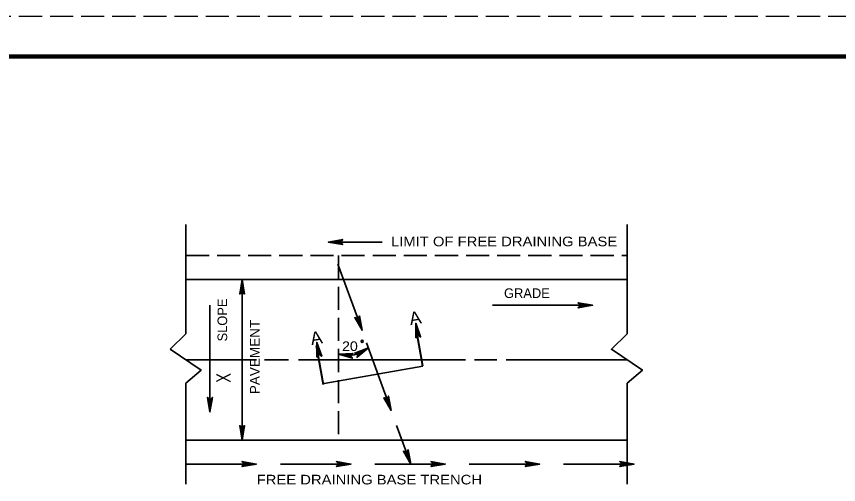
# Model space of a CAD drawing. Extents: x -48732 to -48696.6, y -117659.8 to -117637.8.
# Drawn here: x -48717.26 to -48707.01, y -117643.69 to -117637.85 of the extents above; entities that cross this region are included whole.
import ezdxf

# ---------------------------------------------------------------- set-up
doc = ezdxf.new("R2010")
doc.units = 0
doc.header["$LTSCALE"] = 0.048
doc.linetypes.add('LONG_DASHED', pattern=[7.5, 6, -1.5])
doc.layers.add('1', color=7, linetype='Continuous', lineweight=25)
doc.layers.add('3', color=7, linetype='Continuous', lineweight=35)

msp = doc.modelspace()

# ---------------------------------------------------------------- linework, layer by layer
at = {"layer": '1', "linetype": 'LONG_DASHED'}
msp.add_line((-48696.76492, -117637.84817), (-48731.96492, -117637.84817), dxfattribs=at)
at = {"layer": '1', "lineweight": 158}
msp.add_line((-48696.84825, -117638.34817), (-48729.34825, -117638.34817), dxfattribs=at)
at = {"layer": '1', "lineweight": 40}
for p, q in [((-48712.19542, -117642.21033), (-48712.27867, -117641.73825)), ((-48713.434, -117642.44325), (-48713.51975, -117641.95708))]:
    msp.add_line(p, q, dxfattribs=at)
at = {"layer": '3'}
for p, q in [((-48709.64742, -117640.44458), (-48709.64742, -117641.80458)), ((-48713.37342, -117640.66158), (-48712.70242, -117640.66158)), ((-48713.25242, -117640.93658), (-48712.95242, -117641.76258)), ((-48715.14742, -117641.13058), (-48709.64742, -117641.13058)), ((-48714.44742, -117641.13058), (-48714.44742, -117643.13058)), ((-48714.84742, -117641.44858), (-48714.84742, -117642.77958)), ((-48711.32742, -117641.45058), (-48710.07842, -117641.45058)), ((-48712.89542, -117641.91858), (-48712.58942, -117642.76258)), ((-48715.14742, -117642.13058), (-48714.26842, -117642.13058)), ((-48714.16742, -117642.13058), (-48713.86942, -117642.13058)), ((-48713.74442, -117642.13058), (-48711.66042, -117642.13058)), ((-48711.55042, -117642.13058), (-48711.27142, -117642.13058)), ((-48711.15642, -117642.13058), (-48709.64742, -117642.13058)), ((-48713.42542, -117642.42717), (-48712.19542, -117642.21033)), ((-48715.14742, -117642.42358), (-48715.14742, -117643.68158)), ((-48709.64742, -117642.42358), (-48709.64742, -117643.68158)), ((-48712.52142, -117642.94858), (-48712.34542, -117643.43058)), ((-48715.14742, -117643.13058), (-48709.64742, -117643.13058)), ((-48715.14742, -117643.43058), (-48714.26842, -117643.43058)), ((-48713.97042, -117643.43058), (-48713.09142, -117643.43058)), ((-48713.97042, -117643.43058), (-48713.09142, -117643.43058)), ((-48712.79342, -117643.43058), (-48711.91442, -117643.43058)), ((-48712.79342, -117643.43058), (-48711.91442, -117643.43058)), ((-48711.61642, -117643.43058), (-48710.73742, -117643.43058)), ((-48711.61642, -117643.43058), (-48710.73742, -117643.43058)), ((-48710.43942, -117643.43058), (-48709.56042, -117643.43058)), ((-48710.43942, -117643.43058), (-48709.56042, -117643.43058))]:
    msp.add_line(p, q, dxfattribs=at)
at = {"layer": '3', "linetype": 'LONG_DASHED'}
for p, q in [((-48715.14742, -117640.83058), (-48709.64742, -117640.83058)), ((-48713.24742, -117640.83058), (-48713.24742, -117643.13058))]:
    msp.add_line(p, q, dxfattribs=at)
at = {"layer": '3'}
for points in [[(-48715.14742, -117640.44458), (-48715.14742, -117641.80458), (-48715.34342, -117641.99858)], [(-48713.19342, -117640.63158), (-48713.37342, -117640.66158), (-48713.19342, -117640.69158), (-48713.19842, -117640.68758), (-48713.35542, -117640.66158), (-48713.19742, -117640.63558), (-48713.20242, -117640.63958), (-48713.33642, -117640.66158), (-48713.20242, -117640.68358), (-48713.20742, -117640.68058), (-48713.31842, -117640.66158), (-48713.20742, -117640.64258), (-48713.21142, -117640.64658), (-48713.30042, -117640.66158), (-48713.21142, -117640.67658), (-48713.21642, -117640.67258), (-48713.28242, -117640.66158), (-48713.21642, -117640.65058), (-48713.22042, -117640.65458), (-48713.26342, -117640.66158), (-48713.22042, -117640.66858), (-48713.22542, -117640.66458), (-48713.24542, -117640.66158), (-48713.22542, -117640.65858), (-48713.19342, -117640.63158), (-48713.22942, -117640.66158), (-48713.19342, -117640.69158)], [(-48714.41742, -117641.31058), (-48714.44742, -117641.13058), (-48714.47742, -117641.31058), (-48714.47342, -117641.30558), (-48714.44742, -117641.14858), (-48714.42142, -117641.30658), (-48714.42542, -117641.30158), (-48714.44742, -117641.16758), (-48714.46942, -117641.30158), (-48714.46642, -117641.29658), (-48714.44742, -117641.18558), (-48714.42842, -117641.29658), (-48714.43242, -117641.29258), (-48714.44742, -117641.20358), (-48714.46242, -117641.29258), (-48714.45842, -117641.28758), (-48714.44742, -117641.22158), (-48714.43642, -117641.28758), (-48714.44042, -117641.28358), (-48714.44742, -117641.24058), (-48714.45442, -117641.28358), (-48714.45042, -117641.27858), (-48714.44742, -117641.25858), (-48714.44442, -117641.27858), (-48714.41742, -117641.31058), (-48714.44742, -117641.27458), (-48714.47742, -117641.31058)], [(-48710.25842, -117641.48058), (-48710.07842, -117641.45058), (-48710.25842, -117641.42058), (-48710.25342, -117641.42458), (-48710.09642, -117641.45058), (-48710.25442, -117641.47658), (-48710.24942, -117641.47258), (-48710.11542, -117641.45058), (-48710.24942, -117641.42858), (-48710.24442, -117641.43158), (-48710.13342, -117641.45058), (-48710.24442, -117641.46958), (-48710.24042, -117641.46558), (-48710.15142, -117641.45058), (-48710.24042, -117641.43558), (-48710.23542, -117641.43958), (-48710.16942, -117641.45058), (-48710.23542, -117641.46158), (-48710.23142, -117641.45758), (-48710.18842, -117641.45058), (-48710.23142, -117641.44358), (-48710.22642, -117641.44758), (-48710.20642, -117641.45058), (-48710.22642, -117641.45358), (-48710.25842, -117641.48058), (-48710.22242, -117641.45058), (-48710.25842, -117641.42058)], [(-48713.04242, -117641.60358), (-48712.95242, -117641.76258), (-48712.98542, -117641.58358), (-48712.98742, -117641.58858), (-48712.95842, -117641.74558), (-48713.03742, -117641.60658), (-48713.03242, -117641.60958), (-48712.96442, -117641.72858), (-48712.98942, -117641.59458), (-48712.99142, -117641.59958), (-48712.97142, -117641.71158), (-48713.02642, -117641.61258), (-48713.02142, -117641.61558), (-48712.97742, -117641.69358), (-48712.99342, -117641.60558), (-48712.99542, -117641.61158), (-48712.98342, -117641.67658), (-48713.01642, -117641.61858), (-48713.01142, -117641.62158), (-48712.98942, -117641.65958), (-48712.99742, -117641.61658), (-48712.99942, -117641.62258), (-48712.99642, -117641.64258), (-48713.00642, -117641.62458), (-48713.04242, -117641.60358), (-48713.00142, -117641.62758), (-48712.98542, -117641.58358)], [(-48712.22217, -117641.846), (-48712.283, -117641.67392), (-48712.28133, -117641.85642), (-48712.27825, -117641.85083), (-48712.27992, -117641.69167), (-48712.22683, -117641.84275), (-48712.23167, -117641.8385), (-48712.27658, -117641.71042), (-48712.275, -117641.84617), (-48712.27292, -117641.84075), (-48712.27342, -117641.72808), (-48712.2355, -117641.83408), (-48712.24008, -117641.83083), (-48712.27033, -117641.74583), (-48712.26967, -117641.83608), (-48712.26658, -117641.8305), (-48712.26717, -117641.76358), (-48712.24492, -117641.82667), (-48712.24958, -117641.82342), (-48712.26392, -117641.78225), (-48712.26333, -117641.82583), (-48712.26025, -117641.82025), (-48712.26075, -117641.8), (-48712.25433, -117641.81917), (-48712.22217, -117641.846), (-48712.258, -117641.81575), (-48712.28133, -117641.85642)], [(-48709.64742, -117641.80458), (-48709.84342, -117641.99858), (-48709.45742, -117642.25958), (-48709.64642, -117642.42358)], [(-48713.45492, -117642.08625), (-48713.51575, -117641.91417), (-48713.51408, -117642.09667), (-48713.511, -117642.09108), (-48713.51267, -117641.93192), (-48713.45958, -117642.083), (-48713.46442, -117642.07875), (-48713.50933, -117641.95067), (-48713.50775, -117642.08642), (-48713.50567, -117642.081), (-48713.50617, -117641.96833), (-48713.46825, -117642.07433), (-48713.47283, -117642.07108), (-48713.50308, -117641.98608), (-48713.50242, -117642.07633), (-48713.49933, -117642.07075), (-48713.49992, -117642.00383), (-48713.47767, -117642.06692), (-48713.48233, -117642.06367), (-48713.49667, -117642.0225), (-48713.49608, -117642.06608), (-48713.493, -117642.0605), (-48713.4935, -117642.04025), (-48713.48708, -117642.05942), (-48713.45492, -117642.08625), (-48713.49075, -117642.056), (-48713.51408, -117642.09667)], [(-48713.01342, -117642.09858), (-48712.87242, -117641.98258), (-48713.04342, -117642.04558), (-48713.03842, -117642.04658), (-48712.88842, -117641.99158), (-48713.01142, -117642.09358), (-48713.00942, -117642.08758), (-48712.90442, -117641.99958), (-48713.03142, -117642.04758), (-48713.02642, -117642.04858), (-48712.91942, -117642.00958), (-48713.00742, -117642.08158), (-48713.00542, -117642.07558), (-48712.93642, -117642.01858), (-48713.02042, -117642.04958), (-48713.01442, -117642.05058), (-48712.95242, -117642.02758), (-48713.00342, -117642.07058), (-48713.00142, -117642.06458), (-48712.96742, -117642.03658), (-48713.00842, -117642.05158), (-48713.00242, -117642.05258), (-48712.98342, -117642.04658), (-48712.99942, -117642.05958), (-48713.01342, -117642.09858), (-48712.99742, -117642.05358), (-48713.04342, -117642.04558)], [(-48715.34442, -117641.99858), (-48714.95842, -117642.25958), (-48715.14742, -117642.42358)], [(-48713.06542, -117642.05058), (-48713.24742, -117642.05858), (-48713.07242, -117642.11058), (-48713.07642, -117642.10558), (-48713.22942, -117642.06058), (-48713.07042, -117642.05358), (-48713.07542, -117642.05758), (-48713.21142, -117642.06258), (-48713.08042, -117642.10158), (-48713.08442, -117642.09758), (-48713.19342, -117642.06558), (-48713.08042, -117642.06058), (-48713.08542, -117642.06358), (-48713.17542, -117642.06758), (-48713.08842, -117642.09258), (-48713.09242, -117642.08858), (-48713.15642, -117642.06958), (-48713.09042, -117642.06658), (-48713.09542, -117642.06958), (-48713.13842, -117642.07158), (-48713.09642, -117642.08458), (-48713.10042, -117642.07958), (-48713.12042, -117642.07458), (-48713.10042, -117642.07358), (-48713.06542, -117642.05058), (-48713.10442, -117642.07658), (-48713.07242, -117642.11058)], [(-48712.67942, -117642.60358), (-48712.58942, -117642.76258), (-48712.62242, -117642.58358), (-48712.62442, -117642.58858), (-48712.59542, -117642.74558), (-48712.67442, -117642.60658), (-48712.66942, -117642.60958), (-48712.60142, -117642.72858), (-48712.62642, -117642.59458), (-48712.62842, -117642.59958), (-48712.60842, -117642.71158), (-48712.66342, -117642.61258), (-48712.65842, -117642.61558), (-48712.61442, -117642.69358), (-48712.63042, -117642.60558), (-48712.63242, -117642.61158), (-48712.62042, -117642.67658), (-48712.65342, -117642.61858), (-48712.64842, -117642.62158), (-48712.62642, -117642.65958), (-48712.63442, -117642.61658), (-48712.63642, -117642.62258), (-48712.63342, -117642.64258), (-48712.64342, -117642.62458), (-48712.67942, -117642.60358), (-48712.63842, -117642.62758), (-48712.62242, -117642.58358)], [(-48714.87742, -117642.59958), (-48714.84742, -117642.77958), (-48714.81742, -117642.59958), (-48714.82142, -117642.60458), (-48714.84742, -117642.76158), (-48714.87342, -117642.60358), (-48714.86942, -117642.60858), (-48714.84742, -117642.74258), (-48714.82542, -117642.60858), (-48714.82842, -117642.61358), (-48714.84742, -117642.72458), (-48714.86642, -117642.61358), (-48714.86242, -117642.61758), (-48714.84742, -117642.70658), (-48714.83242, -117642.61758), (-48714.83642, -117642.62258), (-48714.84742, -117642.68858), (-48714.85842, -117642.62258), (-48714.85442, -117642.62658), (-48714.84742, -117642.66958), (-48714.84042, -117642.62658), (-48714.84442, -117642.63158), (-48714.84742, -117642.65158), (-48714.85042, -117642.63158), (-48714.87742, -117642.59958), (-48714.84742, -117642.63558), (-48714.81742, -117642.59958)], [(-48714.47742, -117642.95058), (-48714.44742, -117643.13058), (-48714.41742, -117642.95058), (-48714.42142, -117642.95558), (-48714.44742, -117643.11258), (-48714.47342, -117642.95458), (-48714.46942, -117642.95958), (-48714.44742, -117643.09358), (-48714.42542, -117642.95958), (-48714.42842, -117642.96458), (-48714.44742, -117643.07558), (-48714.46642, -117642.96458), (-48714.46242, -117642.96858), (-48714.44742, -117643.05758), (-48714.43242, -117642.96858), (-48714.43642, -117642.97358), (-48714.44742, -117643.03958), (-48714.45842, -117642.97358), (-48714.45442, -117642.97758), (-48714.44742, -117643.02058), (-48714.44042, -117642.97758), (-48714.44442, -117642.98258), (-48714.44742, -117643.00258), (-48714.45042, -117642.98258), (-48714.47742, -117642.95058), (-48714.44742, -117642.98658), (-48714.41742, -117642.95058)], [(-48712.43542, -117643.27158), (-48712.34542, -117643.43058), (-48712.37842, -117643.25158), (-48712.38042, -117643.25658), (-48712.35142, -117643.41358), (-48712.43042, -117643.27458), (-48712.42542, -117643.27758), (-48712.35742, -117643.39658), (-48712.38242, -117643.26258), (-48712.38442, -117643.26758), (-48712.36442, -117643.37958), (-48712.41942, -117643.28058), (-48712.41442, -117643.28358), (-48712.37042, -117643.36158), (-48712.38642, -117643.27358), (-48712.38842, -117643.27958), (-48712.37642, -117643.34458), (-48712.40942, -117643.28658), (-48712.40442, -117643.28958), (-48712.38242, -117643.32758), (-48712.39042, -117643.28458), (-48712.39242, -117643.29058), (-48712.38942, -117643.31058), (-48712.39942, -117643.29258), (-48712.43542, -117643.27158), (-48712.39442, -117643.29558), (-48712.37842, -117643.25158)], [(-48714.44842, -117643.46058), (-48714.26842, -117643.43058), (-48714.44842, -117643.40058), (-48714.44342, -117643.40458), (-48714.28642, -117643.43058), (-48714.44442, -117643.45658), (-48714.43942, -117643.45258), (-48714.30542, -117643.43058), (-48714.43942, -117643.40858), (-48714.43442, -117643.41158), (-48714.32342, -117643.43058), (-48714.43442, -117643.44958), (-48714.43042, -117643.44558), (-48714.34142, -117643.43058), (-48714.43042, -117643.41558), (-48714.42542, -117643.41958), (-48714.35942, -117643.43058), (-48714.42542, -117643.44158), (-48714.42142, -117643.43758), (-48714.37842, -117643.43058), (-48714.42142, -117643.42358), (-48714.41642, -117643.42758), (-48714.39642, -117643.43058), (-48714.41642, -117643.43358), (-48714.44842, -117643.46058), (-48714.41242, -117643.43058), (-48714.44842, -117643.40058)], [(-48713.27142, -117643.46058), (-48713.09142, -117643.43058), (-48713.27142, -117643.40058), (-48713.26642, -117643.40458), (-48713.10942, -117643.43058), (-48713.26742, -117643.45658), (-48713.26242, -117643.45258), (-48713.12842, -117643.43058), (-48713.26242, -117643.40858), (-48713.25742, -117643.41158), (-48713.14642, -117643.43058), (-48713.25742, -117643.44958), (-48713.25342, -117643.44558), (-48713.16442, -117643.43058), (-48713.25342, -117643.41558), (-48713.24842, -117643.41958), (-48713.18242, -117643.43058), (-48713.24842, -117643.44158), (-48713.24442, -117643.43758), (-48713.20142, -117643.43058), (-48713.24442, -117643.42358), (-48713.23942, -117643.42758), (-48713.21942, -117643.43058), (-48713.23942, -117643.43358), (-48713.27142, -117643.46058), (-48713.23542, -117643.43058), (-48713.27142, -117643.40058)], [(-48712.09442, -117643.46058), (-48711.91442, -117643.43058), (-48712.09442, -117643.40058), (-48712.08942, -117643.40458), (-48711.93242, -117643.43058), (-48712.09042, -117643.45658), (-48712.08542, -117643.45258), (-48711.95142, -117643.43058), (-48712.08542, -117643.40858), (-48712.08042, -117643.41158), (-48711.96942, -117643.43058), (-48712.08042, -117643.44958), (-48712.07642, -117643.44558), (-48711.98742, -117643.43058), (-48712.07642, -117643.41558), (-48712.07142, -117643.41958), (-48712.00542, -117643.43058), (-48712.07142, -117643.44158), (-48712.06742, -117643.43758), (-48712.02442, -117643.43058), (-48712.06742, -117643.42358), (-48712.06242, -117643.42758), (-48712.04242, -117643.43058), (-48712.06242, -117643.43358), (-48712.09442, -117643.46058), (-48712.05842, -117643.43058), (-48712.09442, -117643.40058)], [(-48710.91742, -117643.46058), (-48710.73742, -117643.43058), (-48710.91742, -117643.40058), (-48710.91242, -117643.40458), (-48710.75542, -117643.43058), (-48710.91342, -117643.45658), (-48710.90842, -117643.45258), (-48710.77442, -117643.43058), (-48710.90842, -117643.40858), (-48710.90342, -117643.41158), (-48710.79242, -117643.43058), (-48710.90342, -117643.44958), (-48710.89942, -117643.44558), (-48710.81042, -117643.43058), (-48710.89942, -117643.41558), (-48710.89442, -117643.41958), (-48710.82842, -117643.43058), (-48710.89442, -117643.44158), (-48710.89042, -117643.43758), (-48710.84742, -117643.43058), (-48710.89042, -117643.42358), (-48710.88542, -117643.42758), (-48710.86542, -117643.43058), (-48710.88542, -117643.43358), (-48710.91742, -117643.46058), (-48710.88142, -117643.43058), (-48710.91742, -117643.40058)], [(-48709.74042, -117643.46058), (-48709.56042, -117643.43058), (-48709.74042, -117643.40058), (-48709.73542, -117643.40458), (-48709.57842, -117643.43058), (-48709.73642, -117643.45658), (-48709.73142, -117643.45258), (-48709.59742, -117643.43058), (-48709.73142, -117643.40858), (-48709.72642, -117643.41158), (-48709.61542, -117643.43058), (-48709.72642, -117643.44958), (-48709.72242, -117643.44558), (-48709.63342, -117643.43058), (-48709.72242, -117643.41558), (-48709.71742, -117643.41958), (-48709.65142, -117643.43058), (-48709.71742, -117643.44158), (-48709.71342, -117643.43758), (-48709.67042, -117643.43058), (-48709.71342, -117643.42358), (-48709.70842, -117643.42758), (-48709.68842, -117643.43058), (-48709.70842, -117643.43358), (-48709.74042, -117643.46058), (-48709.70442, -117643.43058), (-48709.74042, -117643.40058)]]:
    msp.add_lwpolyline(points, dxfattribs=at)
msp.add_circle((-48712.95092, -117641.90008), 0.01366, dxfattribs=at)
msp.add_arc((-48713.12742, -117641.68758), 0.39, 252.07979, 310.84036, dxfattribs=at)

# ---------------------------------------------------------------- texts
at = {"layer": '1', "width": 1.05}
for p in [(-48712.3495, -117641.69917), (-48713.58217, -117641.94742)]:
    msp.add_text('A', height=0.159, rotation=10, dxfattribs=at).set_placement(p)
at = {"layer": '3'}
for s, width, p in [('LIMIT OF FREE DRAINING BASE', 1.15, (-48712.59142, -117640.71458)), ('20', 1.1, (-48713.20142, -117642.02058)), ('FREE DRAINING BASE TRENCH', 1.15, (-48714.26567, -117643.68467))]:
    msp.add_text(s, height=0.12, dxfattribs=dict(at, width=width)).set_placement(p)
msp.add_text('GRADE', height=0.12, dxfattribs=at).set_placement((-48711.18242, -117641.35958))
msp.add_text('SLOPE', height=0.12, rotation=90, dxfattribs=at).set_placement((-48714.63342, -117641.90158))
for s, height, width, p in [('PAVEMENT', 0.12, 1.05, (-48714.22842, -117642.55858)), ('X', 0.18, 0.75, (-48714.58942, -117642.41658))]:
    msp.add_text(s, height=height, rotation=90, dxfattribs=dict(at, width=width)).set_placement(p)

doc.saveas('drawing.dxf')
